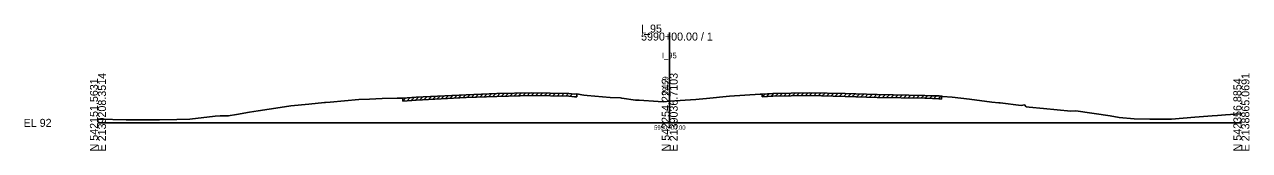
# Model space of a CAD drawing. Extents: x -12534 to 3403, y -1332 to 21983.
# Drawn here: x -25.7 to 402.8, y 18490.3 to 18534.5 of the extents above; entities that cross this region are included whole.
import ezdxf

# ---------------------------------------------------------------- set-up
doc = ezdxf.new("R2010")
doc.units = 0
for name, color, linetype in [('RD_GPK_XS_Cell', 7, 'Continuous'), ('RD_XS_ExGround', 7, 'Continuous'), ('RD_XS_ExPaveRet', 7, 'Continuous'), ('RD_XS_TX_Baseline', 7, 'Continuous'), ('RD_XS_TX_Elev_EX', 7, 'Continuous'), ('RD_XS_TX_Station', 7, 'Continuous')]:
    doc.layers.add(name, color=color, linetype=linetype)

msp = doc.modelspace()

# ---------------------------------------------------------------- linework, layer by layer
at = {"layer": 'RD_GPK_XS_Cell'}
for p, q in [((200, 18500), (200, 18531.63)), ((0, 18500), (200, 18500)), ((200, 18500), (400, 18500))]:
    msp.add_line(p, q, dxfattribs=at)
at = {"layer": 'RD_XS_ExGround'}
msp.add_lwpolyline([(0, 18501.39), (0.48, 18501.33), (9.91, 18501.1), (11.04, 18501.05), (11.81, 18501.05), (20.57, 18501.11), (21.57, 18501.08), (27.62, 18501.18), (32.18, 18501.29), (40.97, 18502.3), (42.8, 18502.48), (43.81, 18502.5), (45.59, 18502.45), (48.5, 18502.95), (53.02, 18503.7), (56.07, 18504.16), (63.73, 18505.4), (67.49, 18505.93), (73.8, 18506.53), (79.24, 18507.1), (79.63, 18507.15), (81.18, 18507.29), (91.26, 18508.13), (95.05, 18508.34), (99.44, 18508.52), (104.68, 18508.65), (106.62, 18508.64), (111.36, 18509), (128.84, 18509.86), (139.57, 18510.29), (151.8, 18510.54), (164.74, 18510.34), (166.71, 18510.08), (167.51, 18510.14), (169.24, 18509.82), (169.97, 18509.71), (171.14, 18509.62), (179.14, 18508.83), (182.79, 18508.75), (183.24, 18508.65), (188.04, 18508), (189.37, 18507.91), (196.03, 18507.45), (197.96, 18507.36), (200, 18507.59), (209.18, 18508.24), (210.33, 18508.33), (212.91, 18508.56), (220.88, 18509.3), (231.69, 18510.05), (232.4, 18510.09), (236.12, 18510.31), (248.93, 18510.53), (261.45, 18510.28), (272.63, 18509.9), (289.31, 18509.62), (291.98, 18509.5), (294.19, 18509.44), (294.47, 18509.4), (295.06, 18509.35), (295.44, 18509.28), (298.78, 18508.95), (304.88, 18508.32), (312.68, 18507.3), (315.2, 18506.97), (315.66, 18506.97), (322.91, 18506.09), (324.12, 18506.32), (324.74, 18505.67), (325.79, 18505.5), (330.75, 18505.05), (340.31, 18504.15), (342.05, 18504.18), (354.13, 18502.41), (357.23, 18501.89), (362.45, 18501.43), (367.92, 18501.34), (371.83, 18501.31), (373.31, 18501.29), (375.55, 18501.35), (383.67, 18502), (389.81, 18502.42), (391.61, 18502.55), (394.46, 18502.78), (399.54, 18503.17), (400, 18503.2)], dxfattribs=at)
at = {"layer": 'RD_XS_ExPaveRet'}
for p, q in [((106.62, 18507.64), (107.7, 18508.72)), ((106.62, 18507.64), (106.62, 18508.64)), ((108.12, 18507.75), (109.2, 18508.84)), ((109.62, 18507.87), (110.7, 18508.95)), ((111.12, 18507.99), (112.17, 18509.04)), ((111.36, 18508), (128.84, 18508.86)), ((112.62, 18508.07), (113.67, 18509.12)), ((114.12, 18508.14), (115.17, 18509.19)), ((115.62, 18508.21), (116.67, 18509.27)), ((117.12, 18508.29), (118.17, 18509.34)), ((118.62, 18508.36), (119.67, 18509.41)), ((120.12, 18508.43), (121.17, 18509.49)), ((121.62, 18508.51), (122.67, 18509.56)), ((123.12, 18508.58), (124.17, 18509.63)), ((124.62, 18508.66), (125.67, 18509.71)), ((126.12, 18508.73), (127.17, 18509.78)), ((127.62, 18508.8), (128.67, 18509.85)), ((128.84, 18508.86), (139.57, 18509.29)), ((129.12, 18508.87), (130.16, 18509.92)), ((130.62, 18508.93), (131.66, 18509.98)), ((132.12, 18508.99), (133.16, 18510.04)), ((133.62, 18509.05), (134.66, 18510.1)), ((135.12, 18509.11), (136.16, 18510.16)), ((136.62, 18509.17), (137.66, 18510.22)), ((138.12, 18509.23), (139.16, 18510.27)), ((139.57, 18509.29), (151.8, 18509.54)), ((139.62, 18509.29), (140.64, 18510.31)), ((141.12, 18509.32), (142.14, 18510.34)), ((142.62, 18509.35), (143.64, 18510.37)), ((144.12, 18509.38), (145.14, 18510.41)), ((145.62, 18509.42), (146.64, 18510.44)), ((147.12, 18509.45), (148.14, 18510.47)), ((148.62, 18509.48), (149.64, 18510.5)), ((150.12, 18509.51), (151.14, 18510.53)), ((151.62, 18509.54), (152.61, 18510.53)), ((151.8, 18509.54), (164.74, 18509.34)), ((153.12, 18509.52), (154.1, 18510.51)), ((154.62, 18509.5), (155.6, 18510.48)), ((156.12, 18509.48), (157.1, 18510.46)), ((157.62, 18509.45), (158.6, 18510.44)), ((159.12, 18509.43), (160.1, 18510.41)), ((160.62, 18509.41), (161.6, 18510.39)), ((162.12, 18509.38), (163.1, 18510.37)), ((163.62, 18509.36), (164.6, 18510.35)), ((164.74, 18509.34), (166.71, 18509.08)), ((165.12, 18509.29), (166, 18510.18)), ((166.71, 18509.08), (167.51, 18509.14)), ((167.51, 18510.14), (167.51, 18509.14)), ((232.4, 18509.09), (233.47, 18510.16)), ((232.4, 18509.09), (232.4, 18510.09)), ((232.4, 18509.09), (236.12, 18509.31)), ((233.9, 18509.18), (234.97, 18510.25)), ((235.4, 18509.27), (236.45, 18510.32)), ((236.12, 18509.31), (248.93, 18509.53)), ((236.9, 18509.33), (237.92, 18510.34)), ((238.4, 18509.35), (239.42, 18510.37)), ((239.9, 18509.38), (240.92, 18510.39)), ((241.4, 18509.4), (242.42, 18510.42)), ((242.9, 18509.43), (243.92, 18510.44)), ((244.4, 18509.45), (245.42, 18510.47)), ((245.9, 18509.48), (246.92, 18510.49)), ((247.4, 18509.5), (248.42, 18510.52)), ((248.9, 18509.53), (249.89, 18510.51)), ((248.93, 18509.53), (261.45, 18509.28)), ((250.4, 18509.5), (251.38, 18510.48)), ((251.9, 18509.47), (252.88, 18510.45)), ((253.4, 18509.44), (254.38, 18510.42)), ((254.9, 18509.41), (255.88, 18510.39)), ((256.4, 18509.38), (257.38, 18510.36)), ((257.9, 18509.35), (258.88, 18510.33)), ((259.4, 18509.32), (260.38, 18510.3)), ((260.9, 18509.29), (261.88, 18510.27)), ((261.45, 18509.28), (272.63, 18508.9)), ((262.4, 18509.25), (263.37, 18510.22)), ((263.9, 18509.2), (264.87, 18510.17)), ((265.4, 18509.15), (266.37, 18510.11)), ((266.9, 18509.1), (267.87, 18510.06)), ((268.4, 18509.05), (269.37, 18510.01)), ((269.9, 18508.99), (270.87, 18509.96)), ((271.4, 18508.94), (272.37, 18509.91)), ((272.63, 18508.9), (289.31, 18508.62)), ((272.9, 18508.9), (273.89, 18509.88)), ((274.4, 18508.87), (275.39, 18509.86)), ((275.9, 18508.85), (276.89, 18509.83)), ((277.4, 18508.82), (278.39, 18509.81)), ((278.9, 18508.8), (279.89, 18509.78)), ((280.4, 18508.77), (281.39, 18509.76)), ((281.9, 18508.75), (282.89, 18509.73)), ((283.4, 18508.72), (284.39, 18509.71)), ((284.9, 18508.7), (285.89, 18509.68)), ((286.4, 18508.67), (287.39, 18509.66)), ((287.9, 18508.65), (288.89, 18509.63)), ((289.31, 18508.62), (291.98, 18508.5)), ((289.4, 18508.62), (290.36, 18509.58)), ((290.9, 18508.55), (291.86, 18509.51)), ((291.98, 18508.5), (294.19, 18508.44)), ((292.4, 18508.49), (293.38, 18509.46)), ((293.9, 18508.45), (294.83, 18509.37)), ((294.19, 18508.44), (294.47, 18508.4)), ((294.47, 18508.4), (295.06, 18508.35)), ((295.06, 18509.35), (295.06, 18508.35)), ((106.62, 18507.64), (111.36, 18508))]:
    msp.add_line(p, q, dxfattribs=at)

# ---------------------------------------------------------------- texts
at = {"layer": 'RD_GPK_XS_Cell'}
for s, p in [('I_95', (190, 18531.63)), ('5990+00.00 / 1', (190, 18528.83)), ('EL 92', (-26, 18498.6))]:
    msp.add_text(s, height=2.8, dxfattribs=at).set_placement(p)
for s, p in [('E 2139208.3514', (2.8, 18490)), ('E 2139036.7103', (202.8, 18490)), ('E 2138865.0691', (402.8, 18490)), ('N 542151.5631', (0, 18490)), ('N 542254.2242', (200, 18490)), ('N 542356.8854', (400, 18490))]:
    msp.add_text(s, height=2.8, rotation=90, dxfattribs=at).set_placement(p)
at = {"layer": 'RD_XS_TX_Baseline'}
msp.add_text('I_95', height=2, dxfattribs=at).set_placement((197.28, 18522.59))
at = {"layer": 'RD_XS_TX_Elev_EX'}
msp.add_text('99.59', height=2, rotation=90, dxfattribs=at).set_placement((199.5, 18509.59))
at = {"layer": 'RD_XS_TX_Station'}
msp.add_text('5990+00.00', height=1.5, dxfattribs=at).set_placement((194.56, 18497.59))

doc.saveas('drawing.dxf')
